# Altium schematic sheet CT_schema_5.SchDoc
size 577 x 363 mm
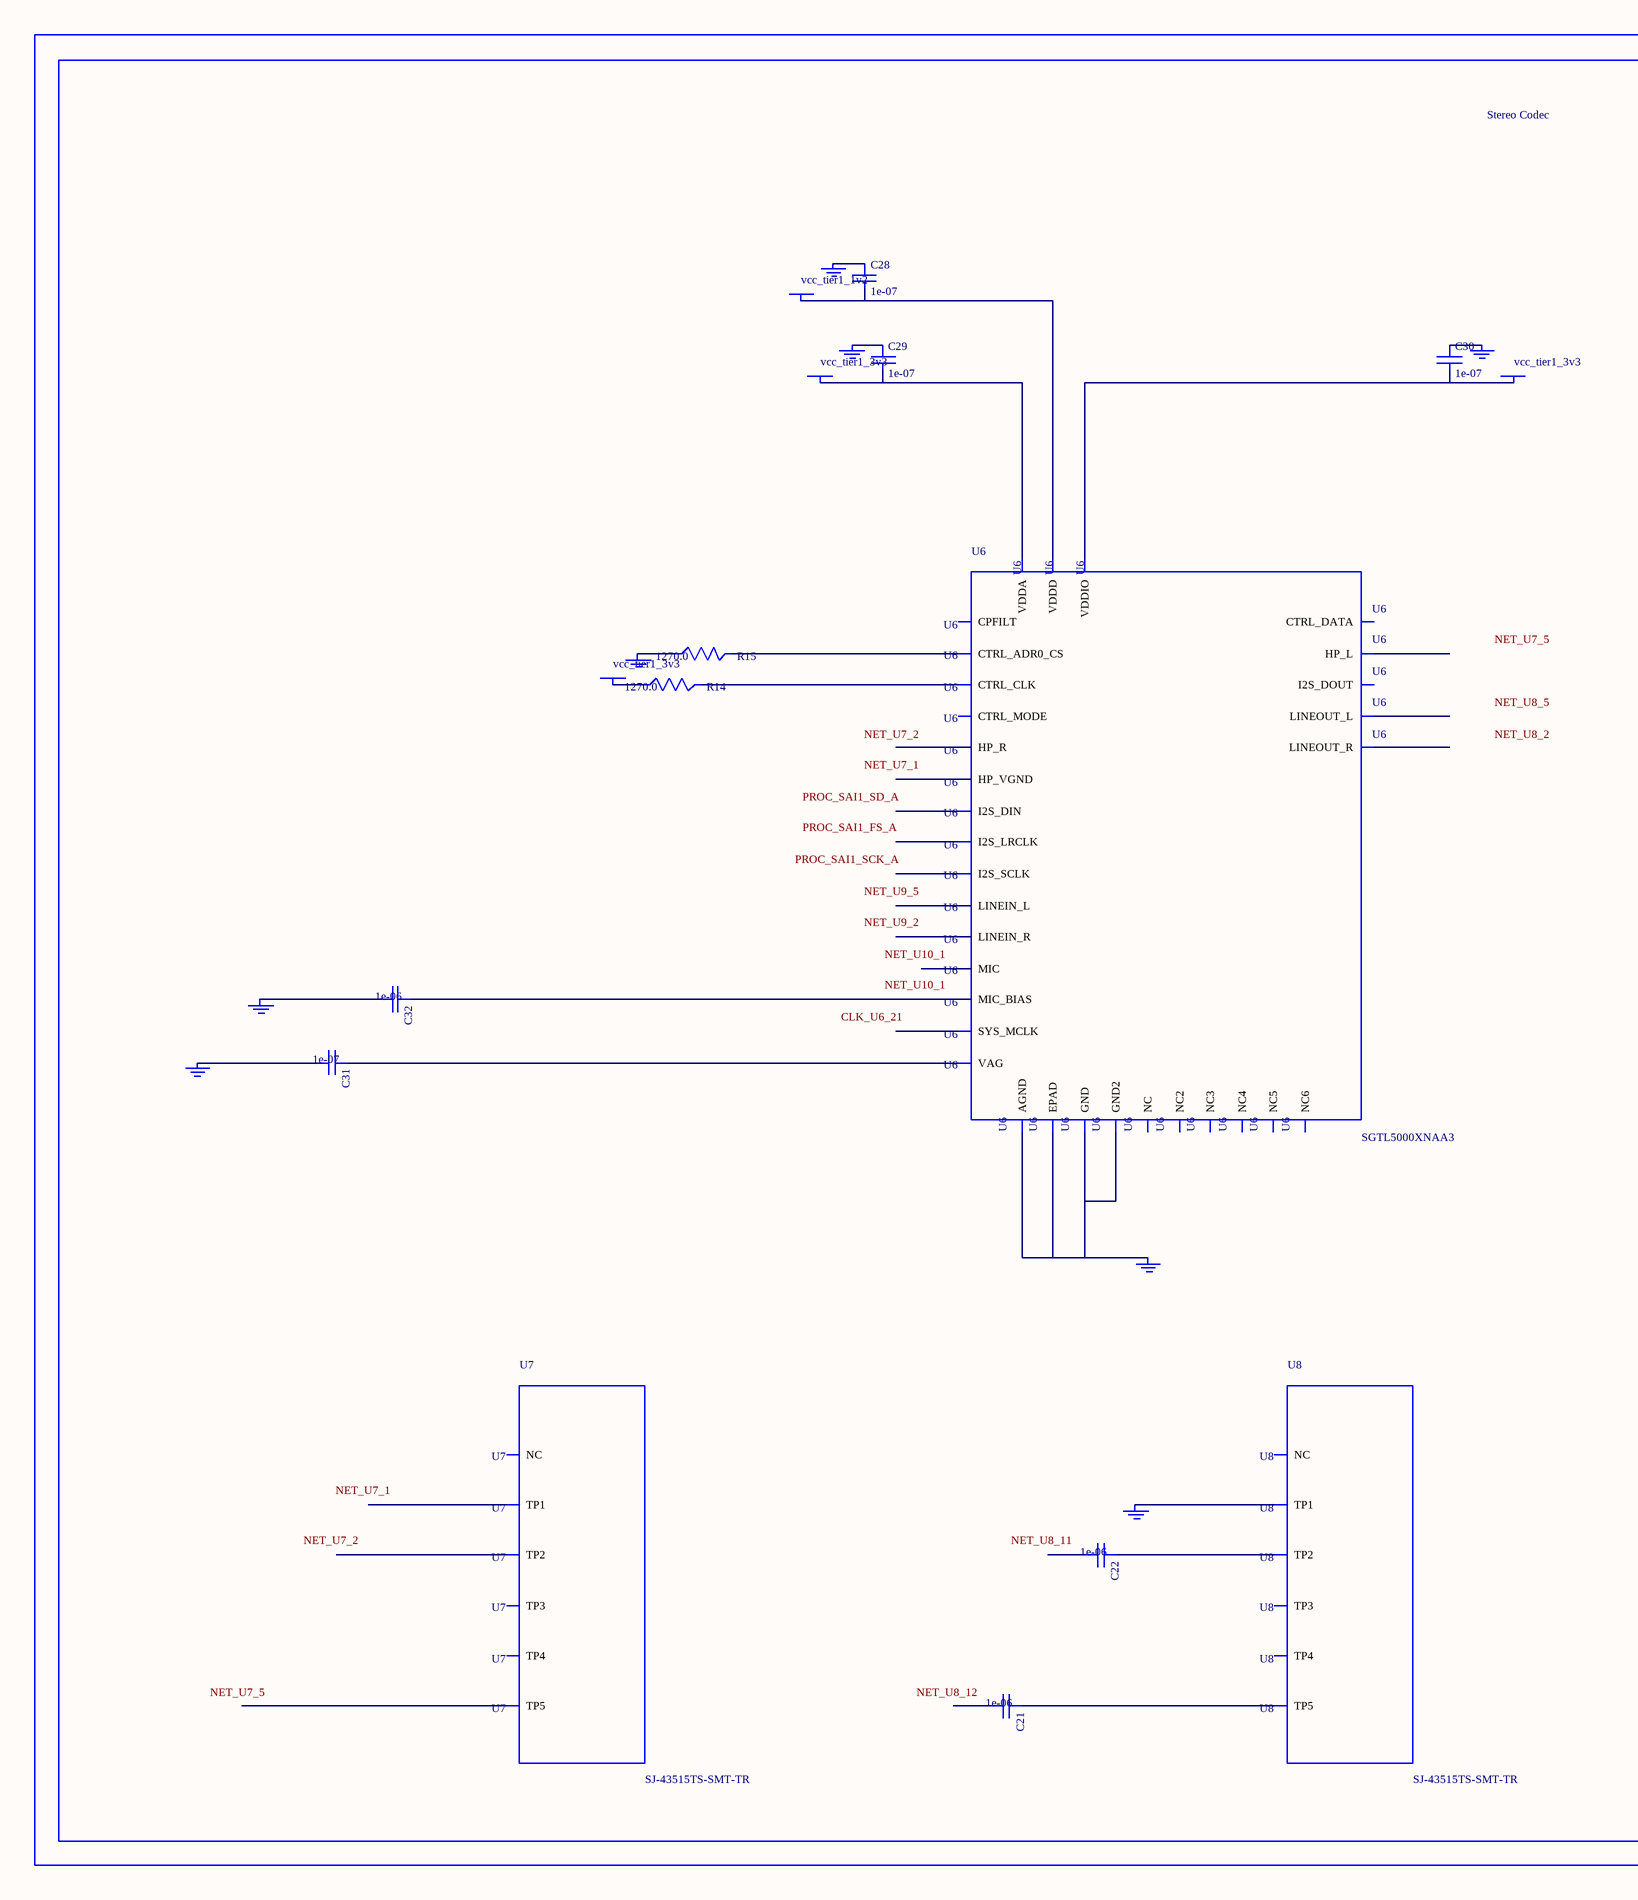
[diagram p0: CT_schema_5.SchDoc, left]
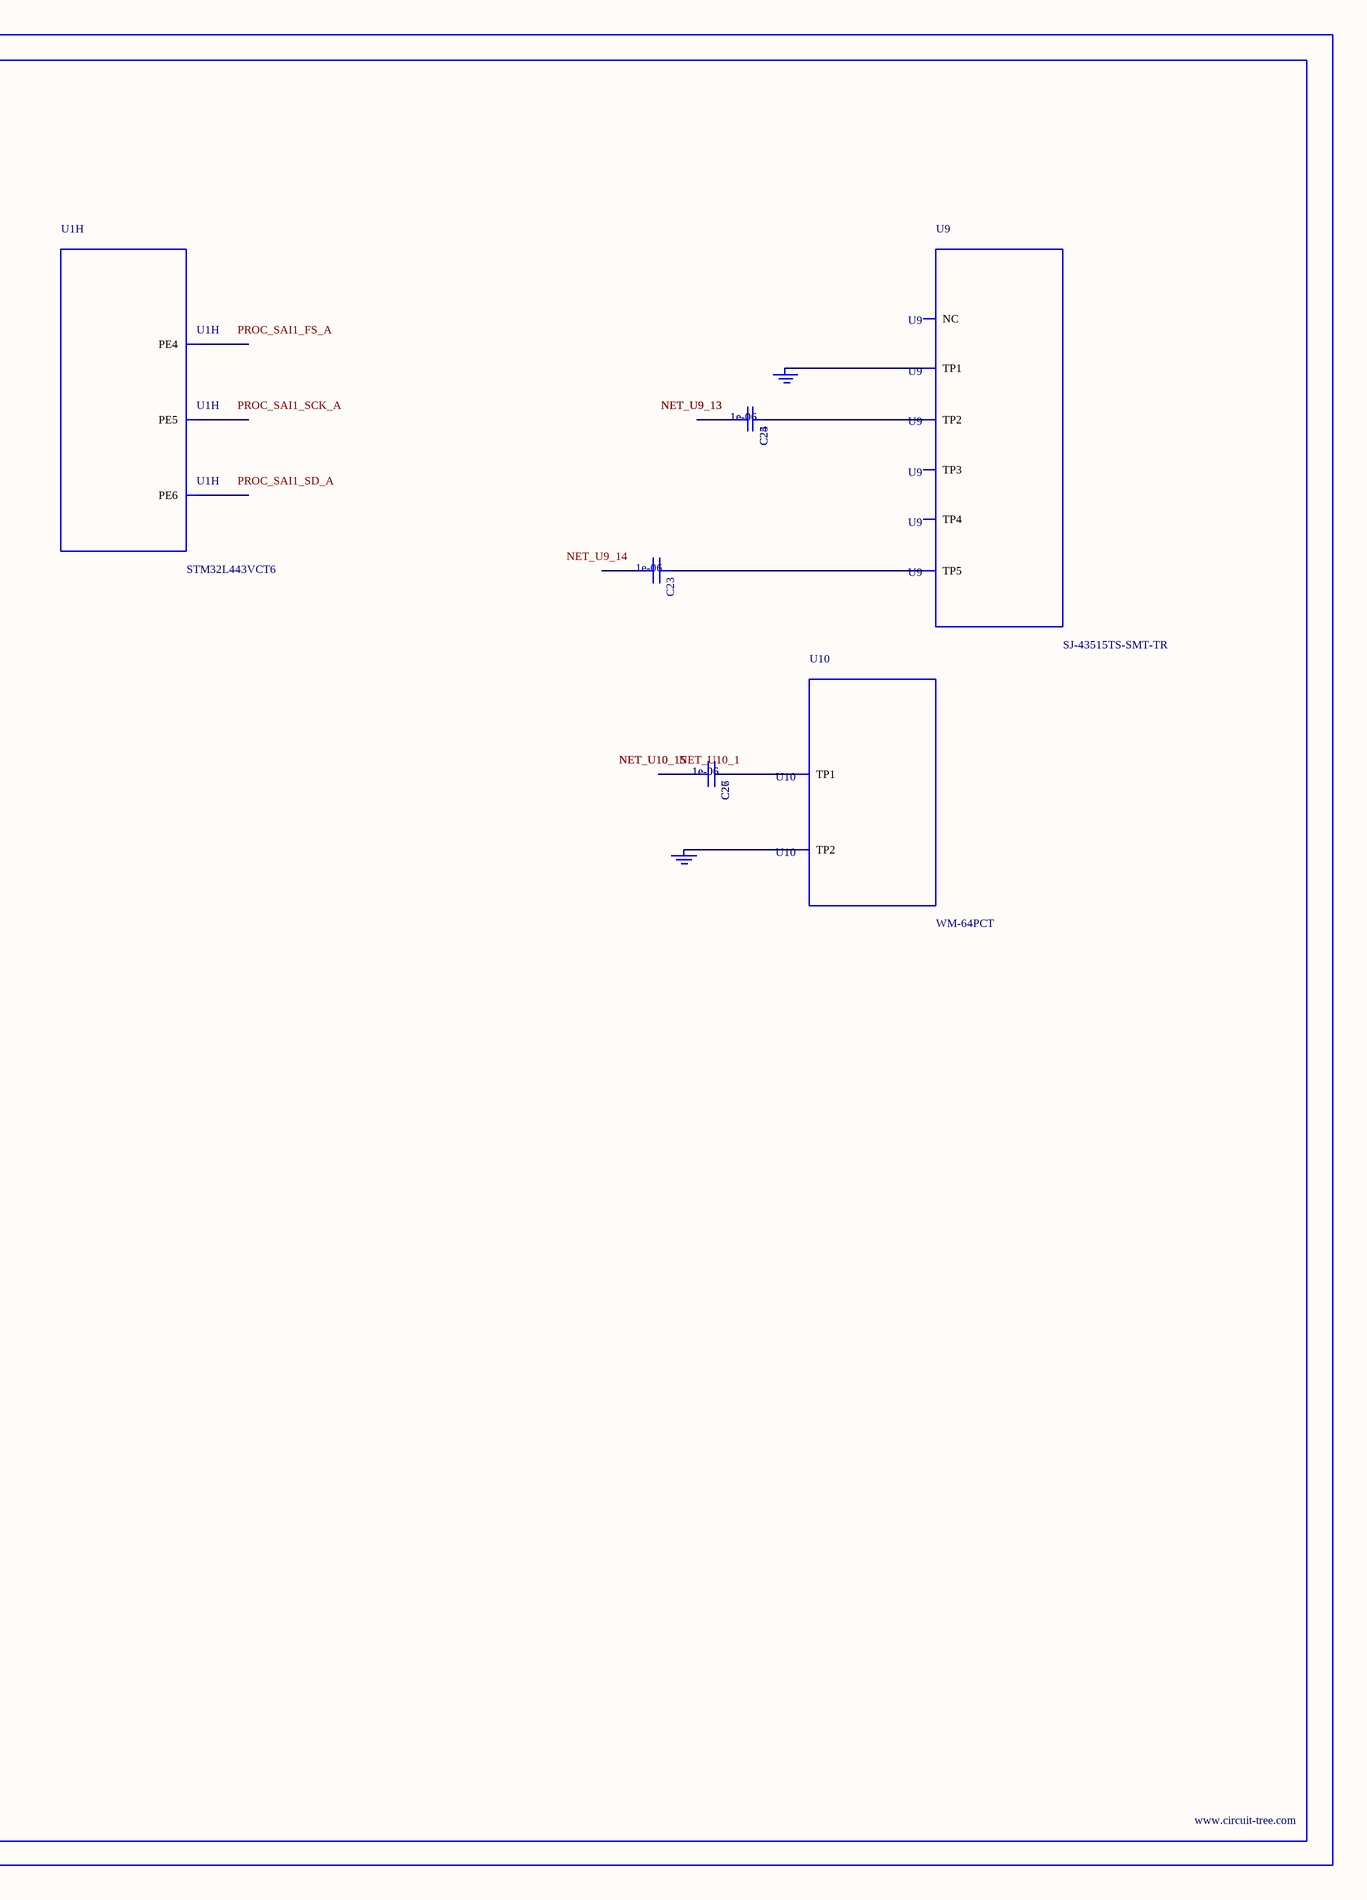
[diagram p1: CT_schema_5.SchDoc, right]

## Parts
BORDER4  (no value)
C21  1e-06  [C0603]
C22  1e-06  [C0603]
C23  1e-06  [C0603]
C24  1e-06  [C0603]
C25  1e-06  [C0603]
C26  1e-06  [C0603]
C27  1e-06  [C0603]
C28  1e-07  [C0402]
C29  1e-07  [C0402]
C30  1e-07  [C0402]
C31  1e-07  [C0402]
C32  1e-06  [C0603]
GND_INSTANCE_4_0  (no value)
GND_INSTANCE_4_1  (no value)
GND_INSTANCE_4_2  (no value)
GND_INSTANCE_4_3  (no value)
GND_INSTANCE_4_4  (no value)
GND_INSTANCE_4_5  (no value)
GND_INSTANCE_4_6  (no value)
GND_INSTANCE_4_7  (no value)
GND_INSTANCE_4_8  (no value)
GND_INSTANCE_4_9  (no value)
GND_INSTANCE_4_10  (no value)
POWER_INSTANCE_4_0  vcc_tier1_3v3
POWER_INSTANCE_4_1  vcc_tier1_3v3
POWER_INSTANCE_4_2  vcc_tier1_3v3
POWER_INSTANCE_4_3  vcc_tier1_1v2
R14  1270.0  [R0603]
R15  1270.0  [R0603]
U1  STM32L443VCT6  [LQFP100]  (part H of 9)
U6  SGTL5000XNAA3  [QFN-32]
U7  SJ-43515TS-SMT-TR  [SJ-43515TS-SMT-TR]
U8  SJ-43515TS-SMT-TR  [SJ-43515TS-SMT-TR]
U9  SJ-43515TS-SMT-TR  [SJ-43515TS-SMT-TR]
U10  WM-64PCT  [WM-64PC]

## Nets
NetC21_1: C21.1 U8.5(TP5)
NetC22_1: C22.1 U8.2(TP2)
NetC23_1: C23.1 U9.5(TP5)
NetC24_1: C24.1 C25.1 U9.2(TP2)
NetC24_2: C24.2 C25.2
NetC26_1: C26.1 C27.1 U10.1(TP1)
NetC26_2: C26.2 C27.2
NetC28_1: C28.1 GND_INSTANCE_4_5.0(GND)
NetC28_2: C28.2 POWER_INSTANCE_4_3.0(PWR) U6.30(VDDD)
NetC29_1: C29.1 GND_INSTANCE_4_1.0(GND)
NetC29_2: C29.2 POWER_INSTANCE_4_0.0(PWR) U6.5(VDDA)
NetC30_1: C30.1 GND_INSTANCE_4_4.0(GND)
NetC30_2: C30.2 POWER_INSTANCE_4_1.0(PWR) U6.20(VDDIO)
NetC31_1: C31.1 U6.10(VAG)
NetC31_2: C31.2 GND_INSTANCE_4_2.0(GND)
NetC32_1: C32.1 U6.16(MIC_BIAS)
NetC32_2: C32.2 GND_INSTANCE_4_3.0(GND)
NetGND_INSTANCE_4_0_0: GND_INSTANCE_4_0.0(GND) U6.1(GND) U6.3(GND2) U6.7(AGND) U6.EXP(EPAD)
NetGND_INSTANCE_4_6_0: GND_INSTANCE_4_6.0(GND) R15.1
NetGND_INSTANCE_4_7_0: GND_INSTANCE_4_7.0(GND) U8.1(TP1)
NetGND_INSTANCE_4_8_0: GND_INSTANCE_4_8.0(GND) GND_INSTANCE_4_9.0(GND) U9.1(TP1)
NetGND_INSTANCE_4_10_0: GND_INSTANCE_4_10.0(GND) U10.2(TP2)
NetPOWER_INSTANCE_4_2_0: POWER_INSTANCE_4_2.0(PWR) R14.1
NetR14_2: R14.2 U6.29(CTRL_CLK)
NetR15_2: R15.2 U6.31(CTRL_ADR0_CS)

Not connected (* = marked no-connect by the designer): C21 2; C22 2; C23 2; U1 3(PE4) 4(PE5) 5(PE6); U6 2(HP_R) 4(HP_VGND) 6(HP_L) 8(NC) 9(NC2) 11(LINEOUT_R) 12(LINEOUT_L) 13(LINEIN_R) 14(LINEIN_L) 15(MIC) 17(NC3) 18(CPFILT) 19(NC4) 21(SYS_MCLK) 22(NC5) 23(I2S_LRCLK) 24(I2S_SCLK) 25(I2S_DOUT) 26(I2S_DIN) 27(CTRL_DATA) 28(NC6) 32(CTRL_MODE); U7 1(TP1) 2(TP2) 3(TP3) 4(TP4) 5(TP5) 6(NC); U8 3(TP3) 4(TP4) 6(NC); U9 3(TP3) 4(TP4) 6(NC)

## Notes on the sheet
- Labels drawn without touching a wire or pin: CLK_U6_21, NET_U7_1, NET_U7_2, NET_U7_5, NET_U8_2, NET_U8_5, NET_U8_11, NET_U8_12, NET_U9_2, NET_U9_5, NET_U9_14, NET_U10_1, PROC_SAI1_FS_A, PROC_SAI1_SCK_A, PROC_SAI1_SD_A

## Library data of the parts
BORDER4 = BORDER_PAGE4
C21-C27 C32 = C0603C105K3RACTU
C28-C31 = C0402C104K3RACTU
GND_INSTANCE_4_0-GND_INSTANCE_4_10 = GND
POWER_INSTANCE_4_0-POWER_INSTANCE_4_3 = PWR
R14 R15 = RC0603FR-071K27L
